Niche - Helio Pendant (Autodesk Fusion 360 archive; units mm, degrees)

design "Helio" references "Luxe Single Pendant Cordset - 4ft Standard", "Helio", "Niche - Chief Architect - Luxe Single Pendant Cordset"
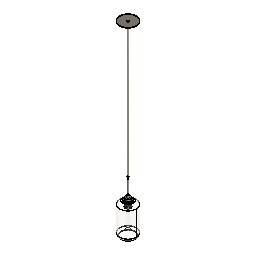
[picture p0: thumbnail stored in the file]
external_derived "ExternalDerived1" bodies "Helio"
external_derived "ExternalDerived2" bodies "Socket Body", "Shade Ring", "Shade Ring +Collar", "Socket", "Body1", "Metal Strain Relief", "Fabric Cord (1)", "Stem (Threaded)"
move "Move1"
external_derived "ExternalDerived3" bodies "T9-Bulb"
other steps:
derived_base_feature "Derived Base Feature1" bodies "Body2", "Helio"
derived_base_feature "Derived Base Feature2" bodies "Socket Body", "Shade Ring", "Shade Ring +Collar", "Socket", "Body1", "Metal Strain Relief", "Fabric Cord (1)", "Stem (Threaded)"
derived_base_feature "Derived Base Feature3" bodies "T9-Bulb"
named bodies: "Body2", "Helio", "Socket Body", "Shade Ring", "Shade Ring +Collar", "Socket", "Body1", "Metal Strain Relief", "Fabric Cord (1)", "Stem (Threaded)", "Cap (Threaded)", "T9-Bulb"

design "Luxe Single Pendant Cordset - 4ft Standard" references "Luxe Canopy - Single Pendant Cordset"
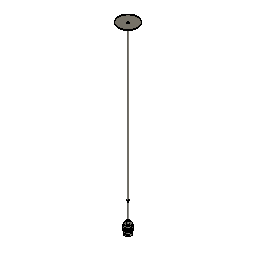
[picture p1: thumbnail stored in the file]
external_derived "ExternalDerived2" bodies "Cap (Threaded)"
move "Move1"
move "Move2"
offset_faces "OffsetFaces1" distance 1051.56
move "Move3"
move "Move4"
move "Move5"
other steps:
derived_base_feature "Derived Base Feature9" bodies "Socket Body", "Shade Ring", "Shade Ring +Collar", "Socket"
derived_base_feature "Derived Base Feature10" bodies "Body1"
derived_base_feature "Derived Base Feature12" bodies "Metal Strain Relief"
derived_base_feature "Derived Base Feature13" bodies "Fabric Cord (1)"
derived_base_feature "Derived Base Feature14" bodies "Stem (Threaded)"
derived_base_feature "Derived Base Feature15" bodies "Cap 9Threaded)", "Cap (Threaded)"
named bodies: "Socket Body", "Shade Ring", "Shade Ring +Collar", "Socket", "Metal Strain Relief", "Fabric Cord (1)", "Stem (Threaded)", "Cap 9Threaded)", "Body1", "Cap (Threaded)", "5M Set Screw"

design "Luxe Canopy - Single Pendant Cordset" references "Luxe Cordset", "M5 Set Screw", "Plastic Strain Relief", "Canopy Mounting Bar", "Canopy Mounting Bar Screw"
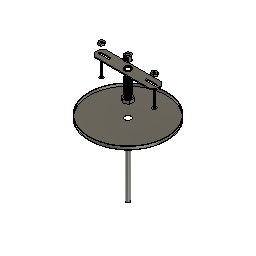
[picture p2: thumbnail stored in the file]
sketch "Sketch1" plane through (0, 0, 0) normal (0, 0, 1) x axis (1, 0, 0)
  circle C1 centre (0, 0) radius 63.5
  point P1 (0, 0)
  point P2 (0, 0)
  coincident P1 P2
  dimension "d1" diameter C1 = 127
extrude "Extrude1" new body sketch "Sketch1" along normal blind 5.08
shell "Shell1" innerThickness 0.762
hole "Hole1" HoleDepth 35.56 HoleDiameter 10.16 TipAngle 118
component_from_bodies "Body->Comp1"
component_insert "Component Insert1"
component_insert "Component Insert2"
component_insert "Component Insert3"
sketch "Sketch2" plane through (0, 0, 0) normal (0, 0, 1) x axis (1, 0, 0)
  circle C1 centre (0, 0) radius 3.175
  point P1 (0, 0)
  point P2 (0, 0)
  coincident P1 P2
  dimension "d8" diameter C1 = 6.35
extrude "Extrude2" new body sketch "Sketch2" along normal blind 127 and against normal blind 127 bodies "Fabric Cord"
component_insert "Component Insert4"
component_insert "Component Insert5"
position "Position1"
sketch "Sketch3" plane through (0, 0, 0.762) normal (0, 0, 1) x axis (-1, 0, 0)
  circle C1 centre (-0.0475, 0.2257) radius 5.08
  circle C2 centre (0, 0) radius 62.738
  circle C3 centre (0, 0) radius 4.826
  concentric C2 C3
  dimension "d13" diameter C3 = 9.652
extrude "Extrude3" new body sketch "Sketch3" profile of C3 along normal blind 25.4 bodies "Threaded Nipple"
shell "Shell2" innerThickness 1.27
thread "Thread1"
sketch "Sketch5" plane through (0, 0, 127) normal (0, 0, 1) x axis (-1, 0, 0)
  line L1 (-6.8191, 3.937) -> (0, 7.874)
  line L2 (-6.8191, -3.937) -> (-6.8191, 3.937)
  line L3 (0, -7.874) -> (-6.8191, -3.937)
  line L4 (6.8191, -3.937) -> (0, -7.874)
  line L5 (6.8191, 3.937) -> (6.8191, -3.937)
  line L6 (0, 7.874) -> (6.8191, 3.937)
  circle C1 centre (0, 0) radius 3.175
  point P2 (0, 0)
  point P9 (0, 0)
  point P3 (0, 7.874)
  coincident P2 P9
  dimension "d20" distance P3 P9 = 7.874
extrude "Extrude4" new body sketch "Sketch5" along normal blind 5.08 bodies "Hex Nut"
move "Move1"
thread "Thread2"
move "Move2" TranslateX 0 TranslateY 0 TranslateZ -55.88
move "Move3" TranslateX 0 TranslateY 0 TranslateZ 60.96
position "Position2"
sketch "Sketch6" plane through (0, 0, 0) normal (0, 0, 1) x axis (1, 0, 0)
  circle C1 centre (0, 0) radius 9.525
  point P1 (0, 0)
  point P2 (0, 0)
  coincident P1 P2
  dimension "d29" diameter C1 = 19.05
extrude "Extrude5" new body sketch "Sketch6" along normal blind 16.129 bodies "Metal Strain Relief"
move "Move4" TranslateX 0 TranslateY 0 TranslateZ -86.36
hole "Hole2" HoleDepth 10.16 HoleDiameter 5.08 TipAngle 118
hole "Hole3" HoleDepth 4.064 HoleDiameter 7.62 TipAngle 180
hole "Hole4" HoleDepth 12.192 HoleDiameter 9.144 TipAngle 180
thread "Thread3" ThreadOffset 0 ThreadLength 6.096
move "Move1" TranslateX 0 TranslateY 0 TranslateZ 68.58
move "Move5" TranslateX 0 TranslateY 0 TranslateZ 138.43
component_insert "Component Insert6"
external_derived "ExternalDerived1" bodies "5M Set Screw"
move "Move6" TranslateX 0 TranslateY 0 TranslateZ -185.42
copy_paste_bodies "CopyPasteBodies1"
move "Move7" TranslateX 0 TranslateY 0 TranslateZ -12.7
offset_faces "OffsetFaces1" distance -152.4
move "Move8"
component_from_bodies "Body->Comp2"
component_from_bodies "Body->Comp3"
component_from_bodies "Body->Comp4"
component_from_bodies "Body->Comp5"
hole "Hole1" HoleDepth 25.4 HoleDiameter 6.35 TipAngle 180
sketch "Sketch7" plane through (0, 0, 0) normal (0, 0, 1) x axis (1, 0, 0)
  line L1 (49.784, 3.9595) -> (52.07, 0)
  line L2 (45.212, 3.9595) -> (49.784, 3.9595)
  line L3 (42.926, 0) -> (45.212, 3.9595)
  line L4 (45.212, -3.9595) -> (42.926, 0)
  line L5 (49.784, -3.9595) -> (45.212, -3.9595)
  line L6 (52.07, 0) -> (49.784, -3.9595)
  point P2 (52.07, 0)
  point P8 (47.498, 0)
  dimension "d63" distance P2 P8 = 4.572
extrude "Extrude6" new body sketch "Sketch7" along normal blind 3.175 bodies "Mounting Hex Nut"
hole "Hole5" HoleDepth 25.4 HoleDiameter 3.81 TipAngle 180
thread "Thread4"
move "Move9"
component_from_bodies "Body->Comp6"
copy_paste "CopyPaste1"
move "Move10"
derived_base_feature "Derived Base Feature3" bodies "Stem (Threaded)", "Cap 9Threaded)"
move "Move11"
component_from_bodies "Body->Comp7"
component_from_bodies "Body->Comp8"
component_from_bodies "Body->Comp9"
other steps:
base_feature "Base Feature1"
base_feature "Base Feature1" bodies "Stem (Threaded)"
base_feature "Base Feature1" bodies "Cap 9Threaded)"
base_feature "Base Feature1" bodies "Fabric Cord"
base_feature "Base Feature1" bodies "Metal Strain Relief"
base_feature "Base Feature1" bodies "Mounting Hex Nut"
base_feature "Base Feature1" bodies "Hex Nut"
base_feature "Base Feature1" bodies "Fabric Cord (1)"
base_feature "Base Feature1" bodies "Threaded Nipple"
derived_base_feature "Derived Base Feature1" bodies "Socket Body", "Shade Ring", "Shade Ring +Collar", "Socket", "Rigid Stem"
derived_base_feature "Derived Base Feature2" bodies "5M Set Screw"
base_feature "Base Feature1" bodies "Fabric Cord", "Fabric Cord (1)"
create_component "CreateComponent1"
remove_body "RemoveBody1"
create_component "CreateComponent2"
remove_body "RemoveBody2"
create_component "CreateComponent3"
remove_body "RemoveBody3"
create_component "CreateComponent4"
remove_body "RemoveBody4"
create_component "CreateComponent5"
remove_body "RemoveBody5"
create_component "CreateComponent6"
remove_body "RemoveBody6"
create_component "CreateComponent7"
remove_body "RemoveBody7"
create_component "CreateComponent8"
remove_body "RemoveBody8"
create_component "CreateComponent9"
remove_body "RemoveBody9"
named bodies: "Fabric Cord", "Threaded Nipple", "Hex Nut", "Metal Strain Relief", "Socket Body", "Shade Ring", "Shade Ring +Collar", "Socket", "Rigid Stem", "5M Set Screw", "Fabric Cord (1)", "Mounting Hex Nut", "Stem (Threaded)", "Cap 9Threaded)"

design "M5 Set Screw"
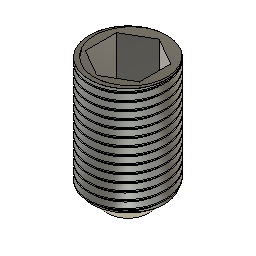
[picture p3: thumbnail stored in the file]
sketch "Sketch1" plane through (0, 0, 0) normal (0, 0, 1) x axis (1, 0, 0)
  circle C1 centre (0, 0) radius 2.5
  point P1 (0, 0)
  point P2 (0, 0)
  coincident P1 P2
  dimension "d1" diameter C1 = 5
extrude "Extrude1" new body sketch "Sketch1" along normal blind 8
sketch "Sketch2" plane through (0, 0, 8) normal (0, 0, 1) x axis (-1, 0, 0)
  line L1 (-1.7321, 1) -> (0, 2)
  line L2 (-1.7321, -1) -> (-1.7321, 1)
  line L3 (0, -2) -> (-1.7321, -1)
  line L4 (1.7321, -1) -> (0, -2)
  line L5 (1.7321, 1) -> (1.7321, -1)
  line L6 (0, 2) -> (1.7321, 1)
  circle C1 centre (0, 0) radius 2.5
  point P2 (0, 0)
  point P9 (0, 0)
  coincident P2 P9
extrude "Extrude2" cut sketch "Sketch2" profile of L1 L2 L3 L4 L5 L6 against normal blind 3
thread "Thread1" ThreadOffset 0.99 ThreadLength 7
chamfer "Chamfer1" distance 1.15

design "Luxe Cordset" references "M5 Set Screw"
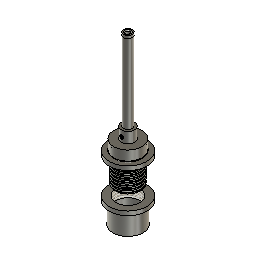
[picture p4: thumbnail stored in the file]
sketch "Sketch1" plane through (0, 0, 0) normal (0, 0, 1) x axis (1, 0, 0)
  circle C1 centre (0, 0) radius 20.6
  point P1 (0, 0)
  point P2 (0, 0)
  coincident P1 P2
  dimension "d11" diameter C1 = 41.2
extrude "Extrude1" new body sketch "Sketch1" along normal blind 14 bodies "Socket Body"
sketch "Sketch2" plane through (0, 0, 14) normal (0, 0, 1) x axis (-1, 0, 0)
  circle C1 centre (0, 0) radius 20.6
  circle C2 centre (0, 0) radius 9.6
  concentric C1 C2
  dimension "d3" diameter C2 = 19.2
extrude "Extrude2" add sketch "Sketch2" profile of C2 along normal blind 15.75
sketch "Sketch3" plane through (0, 0, 29.75) normal (0, 0, 1) x axis (-1, 0, 0)
  circle C1 centre (0, 0) radius 9.6
  circle C2 centre (0, 0) radius 5.75
  concentric C1 C2
  dimension "d6" diameter C2 = 11.5
extrude "Extrude3" new body sketch "Sketch3" profile of C2 along normal blind 114 bodies "Rigid Stem"
move "Move1"
sketch "Sketch4" plane through (0, 0, 203.75) normal (0, 0, 1) x axis (-1, 0, 0)
  circle C1 centre (0, 0) radius 5.75
  circle C2 centre (0, 0) radius 27.5
  dimension "d10" diameter C2 = 55
extrude "Extrude4" new body sketch "Sketch4" profile of C2 along normal blind 6 bodies "Shade Ring"
hole "Hole1" HoleDepth 25 HoleDiameter 42.75 TipAngle 118
sketch "Sketch5" plane through (0, 0, 0) normal (0, 0, 1) x axis (1, 0, 0)
  circle C1 centre (0, 0) radius 22
  point P1 (0, 0)
  point P2 (0, 0)
  coincident P1 P2
  dimension "d18" diameter C1 = 44
move "Move2"
copy_paste_bodies "CopyPasteBodies1"
move "Move3"
sketch "Sketch6" plane through (0, 0, 60) normal (0, 0, -1) x axis (1, 0, 0)
  circle C1 centre (0, 0) radius 20.6
  circle C2 centre (0, 0) radius 21.375
  circle C3 centre (0, 0) radius 20
  concentric C1 C2
  concentric C1 C3
  dimension "d21" diameter C2 = 42.75
  dimension "d24" diameter C3 = 40
cylinder_primitive "CylinderPrimitive1" Height 8 Diameter 42.75
thread "Thread1"
thread "Thread3"
hole "Hole2" HoleDepth 18 HoleDiameter 39 TipAngle 180
move "Move4"
move "Move5"
move "Move6"
hole "Hole3" HoleDepth 114 HoleDiameter 7.6 TipAngle 180
derived_base_feature "Derived Base Feature" bodies "Socket"
move "Move7"
scale "Scale1" ScaleX 1.2 ScaleY 1.2
move "Move8"
sketch "Sketch8" plane through (0, 0, -23.9827) normal (0, 0, -1) x axis (1, 0, 0)
  circle C1 centre (0, -0.036) radius 27.5
  circle C2 centre (0, -0.036) radius 22
  circle C3 centre (0, -0.036) radius 19.5
  dimension "d36" diameter C2 = 44
  dimension "d42" = -2.5
extrude "Extrude7" add sketch "Sketch8" profile of C2 C3 along normal blind 30
offset_faces "OffsetFaces1" distance 2.75
offset_faces "OffsetFaces2" distance -9
thread "Thread2"
move "Move9"
move "Move10"
move "Move11"
scale "Scale2" ScaleZ 1.2
move "Move12"
move "Move13"
move "Move14"
move "Move15"
move "Move16"
split_face "SplitFace1"
move "Move17"
move "Move18"
move "Move19"
move "Move20"
move "Move21"
move "Move22"
move "Move23"
move "Move24"
move "Move25"
move "Move26"
move "Move27"
thread "Thread4"
move "Move28"
move "Move29"
move "Move30"
hole "Hole4" HoleDepth 21 HoleDiameter 39.35 TipAngle 180
hole "Hole5" HoleDepth 9 HoleDiameter 5 TipAngle 180
move "Move31"
move "Move32"
hole "Hole6" HoleDepth 20 HoleDiameter 10 TipAngle 180
move_face "MoveFace3"
move "Move33"
move "Move34"
move "Move35"
move "Move36"
move "Move37"
thread "Thread5" ThreadOffset 0 ThreadLength 6
thread "Thread6" ThreadOffset 0 ThreadLength 6
move "Move38"
move "Move39"
move "Move40"
move "Move41"
component_insert "Component Insert"
thread "Thread7" ThreadOffset 0.5 ThreadLength 5.337
chamfer "Chamfer1" distance 0.5 distance 0.35
sketch "Sketch12" plane through (0, 0, 0) normal (0, 0, 1) x axis (1, 0, 0)
  circle C1 centre (0, 0) radius 6.35
  dimension "d60" diameter C1 = 12.7
extrude "Extrude8" new body sketch "Sketch12" along normal blind 115 bodies "Stem (Threaded)"
hole "Hole7" HoleDepth 115 HoleDiameter 9.65 TipAngle 118
thread "Thread8" ThreadOffset 0 ThreadLength 12.5
thread "Thread9" ThreadOffset 0 ThreadLength 12.5
sketch "Sketch13" plane through (0, 0, 0) normal (0, 0, 1) x axis (1, 0, 0)
  circle C1 centre (0, 0) radius 6.35
  point P1 (0, 0)
  point P2 (0, 0)
  coincident P1 P2
  dimension "d70" diameter C1 = 12.7
extrude "Extrude9" new body sketch "Sketch13" along normal blind 4 bodies "Cap 9Threaded)"
sketch "Sketch14" plane through (0, 0, 4) normal (0, 0, 1) x axis (-1, 0, 0)
  circle C1 centre (0, 0) radius 6.35
  circle C2 centre (0, 0) radius 4.5
  concentric C1 C2
  dimension "d73" diameter C2 = 9
extrude "Extrude10" add sketch "Sketch14" profile of C2 against normal blind 14
thread "Thread10"
hole "Hole8" HoleDepth 115 HoleDiameter 6.5 TipAngle 118 CSDiameter 9 CSAngle 90
move "Move42"
move "Move43"
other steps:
base_feature "Base Feature" bodies "Shade Ring +Collar"
named bodies: "Socket Body", "Shade Ring", "Shade Ring +Collar", "Socket", "Rigid Stem", "Stem (Threaded)", "Cap 9Threaded)"

design "Niche - Chief Architect - Luxe Single Pendant Cordset"
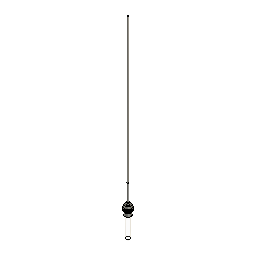
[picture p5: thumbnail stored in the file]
derived_base_feature "Derived Base Feature" bodies "Socket Body", "Shade Ring", "Shade Ring +Collar", "Socket", "Canopy", "Metal Strain Relief", "Fabric Cord (1)", "Stem (Threaded)"
remove_body "RemoveBody1"
remove_body "RemoveBody2"
split "Split1" bodies "Socket Body (1)"
remove_body "RemoveBody3"
align "Align1"
hole "Hole1" HoleDepth 19.05 HoleDiameter 8.89 TipAngle 118
combine "Combine1" bodies "Shade Ring"
split "Split2" bodies "Socket (1)"
remove_body "RemoveBody4"
split "Split3" bodies "Fabric Cord (1) (1)"
remove_body "RemoveBody5"
combine "Combine2" bodies "Socket Body"
align "Align2"
combine "Combine3" bodies "Metal Strain Relief"
sketch "Sketch1" plane through (0, 0, 0) normal (0, 1, 0) x axis (1, 0, 0)
  line L1 (13.1098, 24.9049) -> (-12.2902, 24.9049)
  line L2 (18.1898, 37.1766) -> (18.1898, 29.9849)
  line L3 (-17.3702, 29.9849) -> (-17.3702, 36.7132)
  line L4 (0, 132.969) -> (0, 24.9049)
  arc A1 centre (0, 86.36) radius 46.609 clockwise from (-22.6031, 45.5985) to (23.276, 45.979)
  arc A2 centre (-27.5302, 36.7132) radius 10.16 clockwise from (-22.6031, 45.5985) to (-17.3702, 36.7132)
  arc A3 centre (28.3498, 37.1766) radius 10.16 clockwise from (18.1898, 37.1766) to (23.276, 45.979)
  arc A4 centre (-12.2902, 29.9849) radius 5.08 clockwise from (-12.2902, 24.9049) to (-17.3702, 29.9849)
  arc A5 centre (13.1098, 29.9849) radius 5.08 clockwise from (18.1898, 29.9849) to (13.1098, 24.9049)
  point P5 (18.1898, 43.4469)
  point P3 (-17.3702, 24.9049)
  point P4 (18.1898, 24.9049)
  point P18 (0, 24.9049)
  point P19 (0, 132.969)
  horizontal L1
  vertical L2
  vertical L3
  tangent A1 A2
  tangent L3 A2
  coincident P5 L2
  coincident P5 A1
  tangent L2 A3
  tangent A1 A3
  equal A2 A3
  coincident P3 L1
  coincident P3 L3
  tangent L1 A4
  tangent L3 A4
  coincident P4 L1
  coincident P4 L2
  tangent L1 A5
  tangent L2 A5
  coincident L1 P18
  coincident A1 P19
  perpendicular L1 L4
  dimension "d4" diameter A1 = 93.218
  dimension "d5" distance P3 P4 = 35.56
  dimension "d6" distance P4 P5 = 18.542
  dimension "d7" radius A2 = 10.16
  dimension "d8" radius A4 = 5.08
  dimension "d9" radius A5 = 5.08
revolve "Revolve1" sketch "Sketch1" AlongAngle 360 bodies "G30-Bulb"
move "Move1"
sketch "Sketch2" plane through (0, 0, 0) normal (0, 1, 0) x axis (1, 0, 0)
  line L1 (12.7, 0) -> (-12.7, 0)
  line L2 (12.7, 152.4) -> (12.7, 0)
  line L3 (-12.7, 0) -> (-12.7, 152.4)
  line L4 (0, 165.1) -> (0, 0)
  arc A1 centre (0, 152.4) radius 12.7 clockwise from (-12.7, 152.4) to (12.7, 152.4)
  point P1 (0, 0)
  point P7 (0, 0)
  point P8 (0, 165.1)
  horizontal L1
  vertical L2
  vertical L3
  coincident P1 P7
  midpoint A1 P8
  perpendicular L1 L4
revolve "Revolve2" sketch "Sketch2" AlongAngle 360 bodies "T9-Bulb"
move "Move2"
sketch "Sketch3" plane through (0, 0, 0) normal (0, 1, 0) x axis (1, 0, 0)
  line L1 (12.7, 0) -> (-12.7, 0)
  line L2 (12.7, 254) -> (12.7, 0)
  line L3 (-12.7, 0) -> (-12.7, 254)
  line L4 (0, 266.7) -> (0, 0)
  arc A1 centre (0, 254) radius 12.7 clockwise from (-12.7, 254) to (12.7, 254)
  point P1 (0, 0)
  point P7 (0, 0)
  point P8 (0, 266.7)
  horizontal L1
  vertical L2
  vertical L3
  coincident P1 P7
  midpoint A1 P8
  perpendicular L1 L4
revolve "Revolve3" sketch "Sketch3" AlongAngle 360 bodies "T8-Bulb"
move "Move3"
move "Move4"
move "Move5"
sketch "Sketch4" plane through (0, 0, 0) normal (0, 1, 0) x axis (1, 0, 0)
  line L1 (15.875, -8.763) -> (-15.875, -8.763)
  line L2 (15.875, 22.987) -> (15.875, -8.763)
  line L3 (-15.875, 22.987) -> (15.875, 22.987)
  line L4 (-15.875, -8.763) -> (-15.875, 22.987)
  line L5 (0, 22.987) -> (0, -8.763)
  point P6 (0, -8.763)
  point P7 (0, 22.987)
  point P2 (-15.875, -8.763)
  point P3 (15.875, -8.763)
  point P5 (-15.875, 22.987)
  horizontal L1
  vertical L2
  horizontal L3
  vertical L4
  midpoint L1 P6
  midpoint L3 P7
  dimension "d13" distance P2 P3 = 31.75
  dimension "d14" distance P2 P5 = 31.75
revolve "Revolve4" sketch "Sketch4" AlongAngle 360 bodies "Bulb Extender"
move "Move6"
sketch "Sketch5" plane through (0, 0, 0) normal (0, 1, 0) x axis (1, 0, 0)
  line L1 (-12.7, 35.56) -> (12.7, 35.56)
  line L2 (-12.7, 5.08) -> (-12.7, 35.56)
  line L3 (12.7, 5.08) -> (-12.7, 5.08)
  line L4 (12.7, 35.56) -> (12.7, 5.08)
  line L5 (-12.7, 5.08) -> (12.7, 35.56)
  line L6 (12.7, 5.08) -> (-12.7, 35.56)
  line L7 (0, 35.56) -> (0, 5.08)
  point P6 (0, 20.32)
  point P7 (0, 5.08)
  point P8 (0, 35.56)
  horizontal L1
  perpendicular L1 L2
  parallel L1 L3
  parallel L2 L4
  coincident L5 P6
  coincident L6 P6
  midpoint L3 P7
  midpoint L1 P8
revolve "Revolve5" sketch "Sketch5" AlongAngle 360 bodies "Y-Spliter"
sketch "Sketch6" plane through (0, 0, 0) normal (0, 1, 0) x axis (1, 0, 0)
  line L1 (-55.88, 64.9514) -> (-21.59, 64.9514)
  line L2 (-55.88, 35.7414) -> (-55.88, 64.9514)
  line L3 (-21.59, 35.7414) -> (-55.88, 35.7414)
  line L4 (-21.59, 64.9514) -> (-21.59, 35.7414)
  line L5 (-55.88, 35.7414) -> (-21.59, 64.9514)
  line L6 (-21.59, 35.7414) -> (-55.88, 64.9514)
  line L7 (-38.735, 64.9514) -> (-38.735, 35.7414)
  point P6 (-38.735, 50.3464)
  point P7 (-38.735, 35.7414)
  point P8 (-38.735, 64.9514)
  point P4 (-55.88, 35.7414)
  point P5 (-21.59, 35.7414)
  point P2 (-21.59, 64.9514)
  horizontal L1
  perpendicular L1 L2
  parallel L1 L3
  parallel L2 L4
  coincident L5 P6
  coincident L6 P6
  midpoint L3 P7
  midpoint L1 P8
  dimension "d17" distance P4 P5 = 34.29
  dimension "d18" distance P2 P5 = 29.21
revolve "Revolve6" sketch "Sketch6" AlongAngle 360
chamfer "Chamfer1" distance 7.62
move "Move7"
mirror "Mirror1" mirrorStitchTolerance 0.1016
move "Move8"
combine "Combine4"
move "Move9"
sketch "Sketch7" plane through (0, 0, 0) normal (0, 1, 0) x axis (1, 0, 0)
  line L1 (-15.24, 40.64) -> (-15.24, 48.1816)
  line L2 (12.7, 38.1) -> (-12.7, 38.1)
  line L3 (15.24, 48.1816) -> (15.24, 40.64)
  line L4 (0, 100.1623) -> (0, 38.1)
  arc A1 centre (0, 76.2) radius 23.9623 clockwise from (-19.7282, 62.5988) to (19.7282, 62.5988)
  arc A2 centre (-40.64, 48.1816) radius 25.4 clockwise from (-19.7282, 62.5988) to (-15.24, 48.1816)
  arc A3 centre (40.64, 48.1816) radius 25.4 clockwise from (15.24, 48.1816) to (19.7282, 62.5988)
  arc A4 centre (-12.7, 40.64) radius 2.54 clockwise from (-12.7, 38.1) to (-15.24, 40.64)
  arc A5 centre (12.7, 40.64) radius 2.54 clockwise from (15.24, 40.64) to (12.7, 38.1)
  point P15 (0, 38.1)
  point P16 (0, 100.1623)
  parallel L1 L3
  tangent A1 A2
  tangent L1 A2
  tangent A1 A3
  tangent L3 A3
  tangent L1 A4
  tangent L2 A4
  tangent L2 A5
  tangent L3 A5
  midpoint L2 P15
  midpoint A1 P16
  perpendicular L2 L4
  dimension "d23" radius A2 = 25.4
  dimension "d24" radius A3 = 25.4
  dimension "d25" radius A4 = 2.54
  dimension "d26" radius A5 = 2.54
revolve "Revolve7" sketch "Sketch7" AlongAngle 360 bodies "A15-Bulb"
move "Move10"
copy_paste_bodies "CopyPasteBodies1"
copy_paste_bodies "CopyPasteBodies2"
move "Move11"
mirror "Mirror2" mirrorStitchTolerance 0.1016 bodies "A15-Bulb (1) (1)"
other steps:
base_feature "Base Feature1" bodies "Y-Spliter", "Bulb Extender", "Y-Spliter (1)", "Bulb Extender (1)"
base_feature "Base Feature2" bodies "A15-Bulb", "A15-Bulb (1)"
named bodies: "Socket Body", "Shade Ring", "Shade Ring +Collar", "Socket", "Canopy", "Metal Strain Relief", "Fabric Cord (1)", "Stem (Threaded)", "Adapter", "5M Set Screw", "Body1 (1)", "Socket Body (1)", "Socket (1)", "Fabric Cord (1) (1)", "G30-Bulb", "T9-Bulb", "T8-Bulb", "Bulb Extender", "Y-Spliter", "A15-Bulb", "Y-Spliter (1)", "Bulb Extender (1)", "A15-Bulb (1)", "A15-Bulb (1) (1)"

design "Niche_Helio_Single_Pendant"
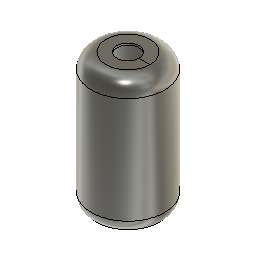
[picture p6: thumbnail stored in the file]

design "Plastic Strain Relief"
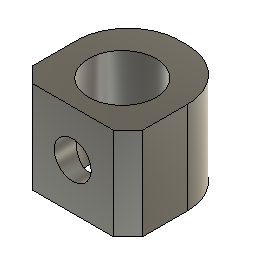
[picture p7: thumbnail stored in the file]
base_feature "Base Feature" bodies "strainrelief"
named bodies: "strainrelief"

design "Canopy Mounting Bar Screw"
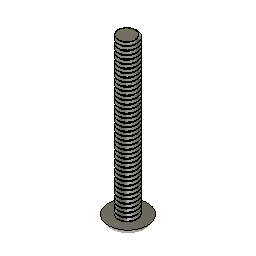
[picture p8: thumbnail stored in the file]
base_feature "Base Feature" bodies "screw1"
named bodies: "screw1"

design "Helio" references "Niche_Helio_Single_Pendant"
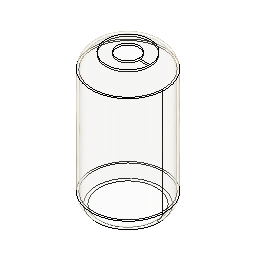
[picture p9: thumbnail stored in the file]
external_derived "ExternalDerived" bodies "Helio"
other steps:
derived_base_feature "Derived Base Feature" bodies "Helio"
named bodies: "Helio"

design "Canopy Mounting Bar"
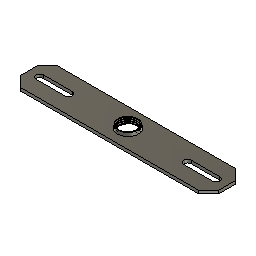
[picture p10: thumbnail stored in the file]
base_feature "Base Feature" bodies "mountingbar"
named bodies: "mountingbar"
